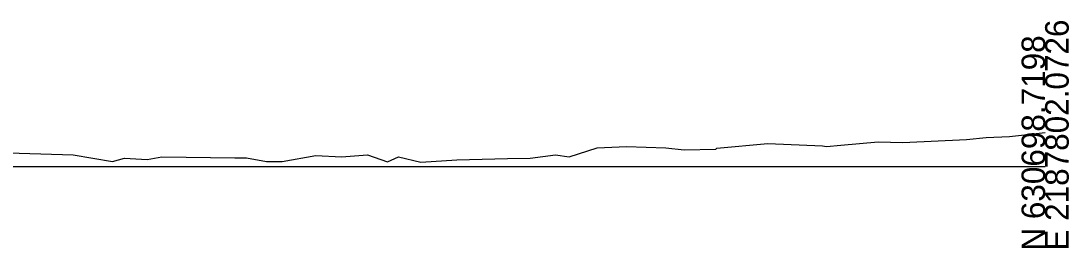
# Model space of a CAD drawing. Extents: x -26 to 4903, y -1010 to 9587.
# Drawn here: x 1178.2 to 1302.8, y 3490.3 to 3517.3 of the extents above; entities that cross this region are included whole.
import ezdxf

# ---------------------------------------------------------------- set-up
doc = ezdxf.new("R2010")
doc.units = 0
doc.layers.add('Exist Cross Section Cell', color=7, linetype='Continuous')
doc.layers.add('Exist XS Ground Line', color=7, linetype='Continuous')

msp = doc.modelspace()

# ---------------------------------------------------------------- linework, layer by layer
at = {"layer": 'Exist Cross Section Cell'}
msp.add_line((1150, 3500), (1300, 3500), dxfattribs=at)
at = {"layer": 'Exist XS Ground Line'}
for p, q in [((1292.97, 3503.44), (1295.75, 3503.58)), ((1295.75, 3503.58), (1300, 3504.07)), ((1246.75, 3502.24), (1250.22, 3502.4)), ((1250.22, 3502.4), (1254.91, 3502.21)), ((1260.96, 3502.18), (1267.02, 3502.73)), ((1267.02, 3502.73), (1273.53, 3502.45)), ((1273.53, 3502.45), (1274.02, 3502.37)), ((1274.02, 3502.37), (1275.72, 3502.53)), ((1275.72, 3502.53), (1280.13, 3502.94)), ((1280.13, 3502.94), (1283.1, 3502.88)), ((1283.1, 3502.88), (1290.66, 3503.23)), ((1290.66, 3503.23), (1292.97, 3503.44)), ((1172.9, 3501.76), (1184.47, 3501.38)), ((1184.47, 3501.38), (1189.12, 3500.62)), ((1193.27, 3500.83), (1194.99, 3501.14)), ((1194.99, 3501.14), (1203.67, 3501.02)), ((1209.28, 3500.59), (1213.31, 3501.31)), ((1213.31, 3501.31), (1216.36, 3501.15)), ((1216.36, 3501.15), (1219.46, 3501.4)), ((1219.46, 3501.4), (1221.81, 3500.56)), ((1221.81, 3500.56), (1223.13, 3501.15)), ((1223.13, 3501.15), (1225.79, 3500.52)), ((1238.8, 3500.98), (1241.8, 3501.38)), ((1241.8, 3501.38), (1243.4, 3501.15)), ((1243.4, 3501.15), (1246.75, 3502.24)), ((1254.91, 3502.21), (1257.1, 3501.97)), ((1257.1, 3501.97), (1260.85, 3502.05)), ((1260.85, 3502.05), (1260.96, 3502.18)), ((1189.12, 3500.62), (1190.54, 3501.01)), ((1190.54, 3501.01), (1193.27, 3500.83)), ((1203.67, 3501.02), (1205.05, 3501.03)), ((1205.05, 3501.03), (1207.43, 3500.61)), ((1207.43, 3500.61), (1209.28, 3500.59)), ((1225.79, 3500.52), (1230.06, 3500.81)), ((1230.06, 3500.81), (1236.07, 3500.95)), ((1236.07, 3500.95), (1238.8, 3500.98))]:
    msp.add_line(p, q, dxfattribs=at)

# ---------------------------------------------------------------- texts
at = {"layer": 'Exist Cross Section Cell'}
for s, p in [('E 2187802.0726', (1302.8, 3490)), ('N 630698.7198', (1300, 3490))]:
    msp.add_text(s, height=2.8, rotation=90, dxfattribs=at).set_placement(p)

doc.saveas('drawing.dxf')
